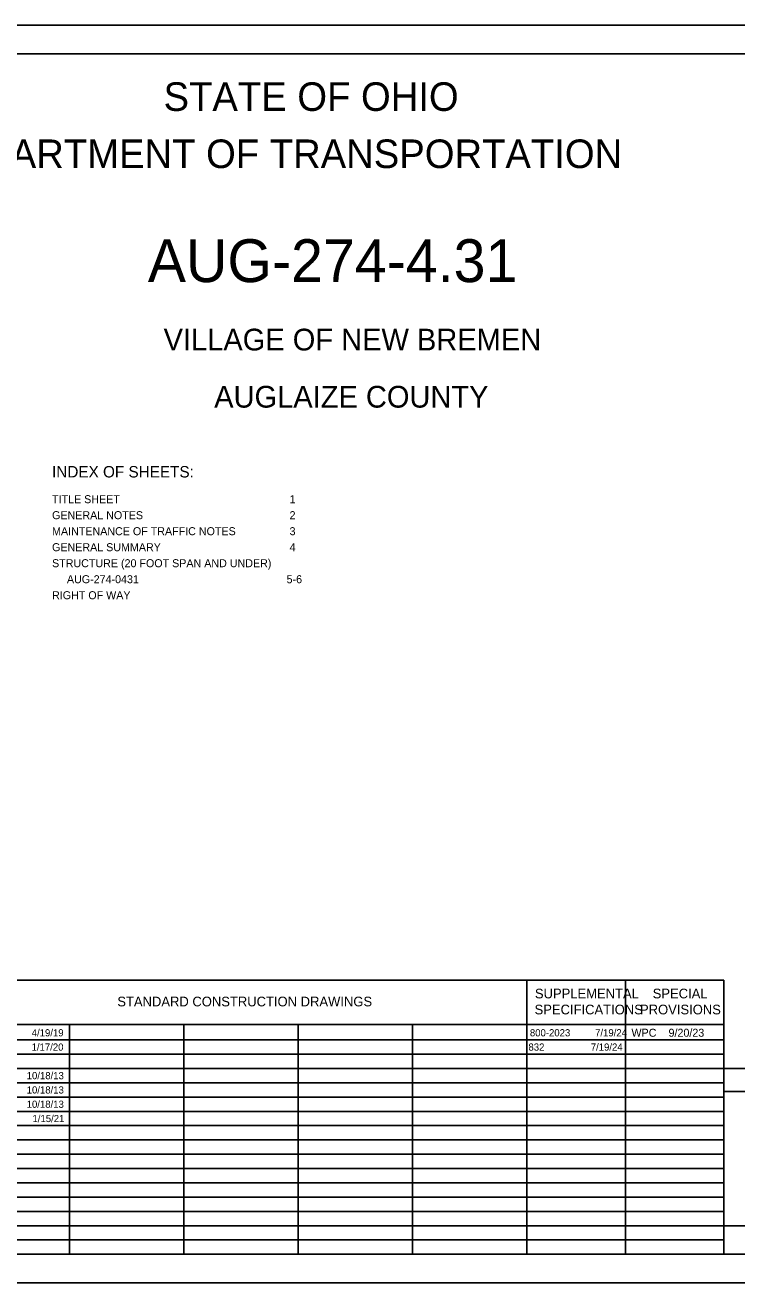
# Model space of a CAD drawing. Extents: x 0 to 34, y 0 to 22.
# Drawn here: x 11.37 to 23.83, y 0 to 22 of the extents above; entities that cross this region are included whole.
import ezdxf

# ---------------------------------------------------------------- set-up
doc = ezdxf.new("R2010")
doc.units = 0
for name, color, linetype in [('Default', 7, 'Continuous'), ('SH_Border', 7, 'Continuous'), ('SH_Cut_Line', 7, 'Continuous'), ('SH_Data', 7, 'Continuous'), ('SH_Text', 7, 'Continuous')]:
    doc.layers.add(name, color=color, linetype=linetype)

msp = doc.modelspace()

# ---------------------------------------------------------------- linework, layer by layer
at = {"layer": 'SH_Border'}
msp.add_lwpolyline([(1.5, 21.5), (33.5, 21.5), (33.5, 0.5), (1.5, 0.5)], close=True, dxfattribs=at)
at = {"layer": 'SH_Cut_Line'}
msp.add_lwpolyline([(0, 0), (34, 0), (34, 22), (0, 22)], close=True, dxfattribs=at)
at = {"layer": 'SH_Data'}
for p, q in [((10.15, 5.292), (23.6, 5.292)), ((20.15, 0.5), (20.15, 5.292)), ((21.875, 0.5), (21.875, 5.292)), ((23.6, 0.5), (23.6, 5.292)), ((10.15, 4.521), (23.6, 4.521)), ((12.15, 0.5), (12.15, 4.521)), ((14.15, 0.5), (14.15, 4.521)), ((16.15, 0.5), (16.15, 4.521)), ((18.15, 0.5), (18.15, 4.521)), ((10.15, 4.25), (23.6, 4.25)), ((10.15, 4), (23.6, 4)), ((10.15, 3.75), (23.6, 3.75)), ((23.6, 0.5), (23.6, 3.75)), ((23.6, 3.75), (26.4, 3.75)), ((10.15, 3.5), (23.6, 3.5)), ((23.6, 3.35), (26.4, 3.35)), ((10.15, 3.25), (23.6, 3.25)), ((10.15, 3), (23.6, 3)), ((10.15, 2.75), (23.6, 2.75)), ((10.15, 2.5), (23.6, 2.5)), ((10.15, 2.25), (23.6, 2.25)), ((10.15, 2), (23.6, 2)), ((10.15, 1.75), (23.6, 1.75)), ((10.15, 1.5), (23.6, 1.5)), ((10.15, 1.25), (23.6, 1.25)), ((10.15, 1), (23.6, 1)), ((10.15, 0.75), (23.6, 0.75)), ((23.6, 0.5), (26.4, 0.5))]:
    msp.add_line(p, q, dxfattribs=at)
msp.add_lwpolyline([(23.6, 0.5), (23.6, 1), (26.4, 1), (26.4, 0.5)], close=True, dxfattribs=at)

# ---------------------------------------------------------------- texts
at = {"layer": 'Default'}
for s, p in [('4/19/19', (11.488, 4.312)), ('800-2023', (20.205, 4.312)), ('7/19/24', (21.346, 4.312)), ('1/17/20', (11.486, 4.062)), ('832', (20.18, 4.062)), ('7/19/24', (21.27, 4.062)), ('10/18/13', (11.4, 3.562)), ('10/18/13', (11.4, 3.312)), ('10/18/13', (11.4, 3.062)), ('1/15/21', (11.502, 2.812))]:
    msp.add_text(s, height=0.125, dxfattribs=at).set_placement(p)
at = {"layer": 'SH_Text'}
for s, height, p in [('STATE OF OHIO', 0.5, (13.795, 20.5)), ('DEPARTMENT OF TRANSPORTATION', 0.5, (9.747, 19.5)), ('AUG-274-4.31', 0.75, (13.519, 17.505)), ('VILLAGE OF NEW BREMEN', 0.38, (13.796, 16.31)), ('AUGLAIZE COUNTY', 0.38, (14.681, 15.31)), ('INDEX OF SHEETS:', 0.2, (11.844, 14.088)), ('TITLE SHEET ', 0.14, (11.844, 13.638)), ('   1   ', 0.14, (15.844, 13.638)), ('GENERAL NOTES   ', 0.14, (11.844, 13.358)), ('   2   ', 0.14, (15.844, 13.358)), ('MAINTENANCE OF TRAFFIC NOTES ', 0.14, (11.844, 13.078)), ('   3   ', 0.14, (15.844, 13.078)), ('GENERAL SUMMARY ', 0.14, (11.844, 12.798)), ('   4   ', 0.14, (15.844, 12.798)), ('STRUCTURE (20 FOOT SPAN AND UNDER) ', 0.14, (11.844, 12.518)), ('     AUG-274-0431         ', 0.14, (11.844, 12.238)), ('  5-6  ', 0.14, (15.844, 12.238)), ('RIGHT OF WAY                        ', 0.14, (11.844, 11.958)), ('SUPPLEMENTAL', 0.17, (20.293, 4.976)), ('SPECIAL', 0.17, (22.354, 4.976)), ('STANDARD CONSTRUCTION DRAWINGS', 0.17, (12.986, 4.836)), ('SPECIFICATIONS', 0.17, (20.287, 4.696)), ('PROVISIONS', 0.17, (22.132, 4.696)), (' WPC', 0.14, (21.93, 4.305)), (' 9/20/23', 0.14, (22.579, 4.305))]:
    msp.add_text(s, height=height, dxfattribs=at).set_placement(p)

doc.saveas('drawing.dxf')
